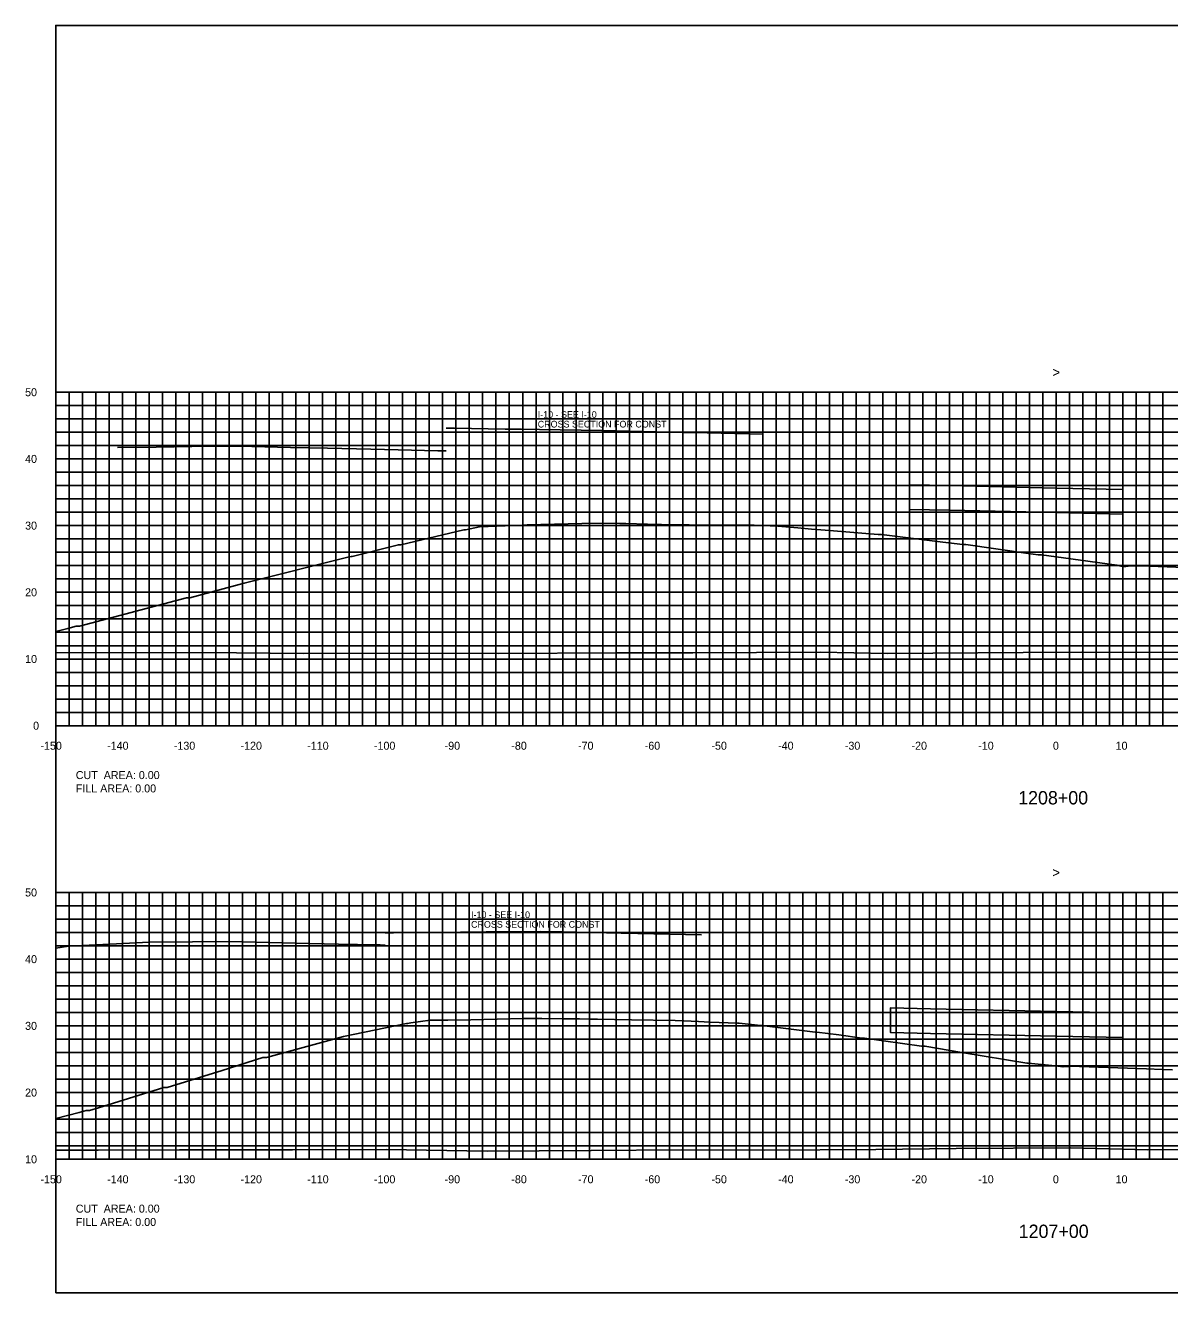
# Model space of a CAD drawing. Extents: x 1797305 to 1804485, y 245831 to 250849.
# Drawn here: x 1803156.4 to 1803328, y 250079.4 to 250269.4 of the extents above; entities that cross this region are included whole.
import ezdxf

# ---------------------------------------------------------------- set-up
doc = ezdxf.new("R2010")
doc.units = 0
for name, color, linetype in [('1', 7, 'Continuous'), ('10', 7, 'Continuous'), ('29', 7, 'Continuous'), ('60', 7, 'Continuous'), ('CL-CNST', 7, 'Continuous'), ('EDPV-LINE', 7, 'Continuous'), ('Level 31', 7, 'Continuous'), ('LIMT-CSLINE', 7, 'Continuous'), ('M-ROADS', 7, 'Continuous'), ('SURVEY - DRAINAGE - Area Shapes', 7, 'Continuous')]:
    doc.layers.add(name, color=color, linetype=linetype)

msp = doc.modelspace()

# ---------------------------------------------------------------- linework, layer by layer
msp.add_lwpolyline([(1803161, 250079.43), (1803461, 250079.43), (1803461, 250269.43), (1803161, 250269.43)], close=True)
at = {"layer": '29'}
for p, q in [((1803161, 250214.43), (1803461, 250214.43)), ((1803161, 250164.43), (1803161, 250214.43)), ((1803163, 250164.43), (1803163, 250214.43)), ((1803165, 250164.43), (1803165, 250214.43)), ((1803167, 250164.43), (1803167, 250214.43)), ((1803169, 250164.43), (1803169, 250214.43)), ((1803171, 250164.43), (1803171, 250214.43)), ((1803173, 250164.43), (1803173, 250214.43)), ((1803175, 250164.43), (1803175, 250214.43)), ((1803177, 250164.43), (1803177, 250214.43)), ((1803179, 250164.43), (1803179, 250214.43)), ((1803181, 250164.43), (1803181, 250214.43)), ((1803183, 250164.43), (1803183, 250214.43)), ((1803185, 250164.43), (1803185, 250214.43)), ((1803187, 250164.43), (1803187, 250214.43)), ((1803189, 250164.43), (1803189, 250214.43)), ((1803191, 250164.43), (1803191, 250214.43)), ((1803193, 250164.43), (1803193, 250214.43)), ((1803195, 250164.43), (1803195, 250214.43)), ((1803197, 250164.43), (1803197, 250214.43)), ((1803199, 250164.43), (1803199, 250214.43)), ((1803201, 250164.43), (1803201, 250214.43)), ((1803203, 250164.43), (1803203, 250214.43)), ((1803205, 250164.43), (1803205, 250214.43)), ((1803207, 250164.43), (1803207, 250214.43)), ((1803209, 250164.43), (1803209, 250214.43)), ((1803211, 250164.43), (1803211, 250214.43)), ((1803213, 250164.43), (1803213, 250214.43)), ((1803215, 250164.43), (1803215, 250214.43)), ((1803217, 250164.43), (1803217, 250214.43)), ((1803219, 250164.43), (1803219, 250214.43)), ((1803221, 250164.43), (1803221, 250214.43)), ((1803223, 250164.43), (1803223, 250214.43)), ((1803225, 250164.43), (1803225, 250214.43)), ((1803227, 250164.43), (1803227, 250214.43)), ((1803229, 250164.43), (1803229, 250214.43)), ((1803231, 250164.43), (1803231, 250214.43)), ((1803233, 250164.43), (1803233, 250214.43)), ((1803235, 250164.43), (1803235, 250214.43)), ((1803237, 250164.43), (1803237, 250214.43)), ((1803239, 250164.43), (1803239, 250214.43)), ((1803241, 250164.43), (1803241, 250214.43)), ((1803243, 250164.43), (1803243, 250214.43)), ((1803245, 250164.43), (1803245, 250214.43)), ((1803247, 250164.43), (1803247, 250214.43)), ((1803249, 250164.43), (1803249, 250214.43)), ((1803251, 250164.43), (1803251, 250214.43)), ((1803253, 250164.43), (1803253, 250214.43)), ((1803255, 250164.43), (1803255, 250214.43)), ((1803257, 250164.43), (1803257, 250214.43)), ((1803259, 250164.43), (1803259, 250214.43)), ((1803261, 250164.43), (1803261, 250214.43)), ((1803263, 250164.43), (1803263, 250214.43)), ((1803265, 250164.43), (1803265, 250214.43)), ((1803267, 250164.43), (1803267, 250214.43)), ((1803269, 250164.43), (1803269, 250214.43)), ((1803271, 250164.43), (1803271, 250214.43)), ((1803273, 250164.43), (1803273, 250214.43)), ((1803275, 250164.43), (1803275, 250214.43)), ((1803277, 250164.43), (1803277, 250214.43)), ((1803279, 250164.43), (1803279, 250214.43)), ((1803281, 250164.43), (1803281, 250214.43)), ((1803283, 250164.43), (1803283, 250214.43)), ((1803285, 250164.43), (1803285, 250214.43)), ((1803287, 250164.43), (1803287, 250214.43)), ((1803289, 250164.43), (1803289, 250214.43)), ((1803291, 250164.43), (1803291, 250214.43)), ((1803293, 250164.43), (1803293, 250214.43)), ((1803295, 250164.43), (1803295, 250214.43)), ((1803297, 250164.43), (1803297, 250214.43)), ((1803299, 250164.43), (1803299, 250214.43)), ((1803301, 250164.43), (1803301, 250214.43)), ((1803303, 250164.43), (1803303, 250214.43)), ((1803305, 250164.43), (1803305, 250214.43)), ((1803307, 250164.43), (1803307, 250214.43)), ((1803309, 250164.43), (1803309, 250214.43)), ((1803311, 250164.43), (1803311, 250214.43)), ((1803313, 250164.43), (1803313, 250214.43)), ((1803315, 250164.43), (1803315, 250214.43)), ((1803317, 250164.43), (1803317, 250214.43)), ((1803319, 250164.43), (1803319, 250214.43)), ((1803321, 250164.43), (1803321, 250214.43)), ((1803323, 250164.43), (1803323, 250214.43)), ((1803325, 250164.43), (1803325, 250214.43)), ((1803327, 250164.43), (1803327, 250214.43)), ((1803161, 250212.43), (1803461, 250212.43)), ((1803161, 250210.43), (1803461, 250210.43)), ((1803161, 250208.43), (1803461, 250208.43)), ((1803161, 250206.43), (1803461, 250206.43)), ((1803161, 250204.43), (1803461, 250204.43)), ((1803161, 250202.43), (1803461, 250202.43)), ((1803161, 250200.43), (1803461, 250200.43)), ((1803161, 250198.43), (1803461, 250198.43)), ((1803161, 250196.43), (1803461, 250196.43)), ((1803161, 250194.43), (1803461, 250194.43)), ((1803161, 250192.43), (1803461, 250192.43)), ((1803161, 250190.43), (1803461, 250190.43)), ((1803161, 250188.43), (1803461, 250188.43)), ((1803161, 250186.43), (1803461, 250186.43)), ((1803161, 250184.43), (1803461, 250184.43)), ((1803161, 250182.43), (1803461, 250182.43)), ((1803161, 250180.43), (1803461, 250180.43)), ((1803161, 250178.43), (1803461, 250178.43)), ((1803161, 250176.43), (1803461, 250176.43)), ((1803161, 250174.43), (1803461, 250174.43)), ((1803161, 250172.43), (1803461, 250172.43)), ((1803161, 250170.43), (1803461, 250170.43)), ((1803161, 250168.43), (1803461, 250168.43)), ((1803161, 250166.43), (1803461, 250166.43)), ((1803161, 250164.43), (1803461, 250164.43)), ((1803161, 250139.43), (1803461, 250139.43)), ((1803161, 250099.43), (1803161, 250139.43)), ((1803163, 250099.43), (1803163, 250139.43)), ((1803165, 250099.43), (1803165, 250139.43)), ((1803167, 250099.43), (1803167, 250139.43)), ((1803169, 250099.43), (1803169, 250139.43)), ((1803171, 250099.43), (1803171, 250139.43)), ((1803173, 250099.43), (1803173, 250139.43)), ((1803175, 250099.43), (1803175, 250139.43)), ((1803177, 250099.43), (1803177, 250139.43)), ((1803179, 250099.43), (1803179, 250139.43)), ((1803181, 250099.43), (1803181, 250139.43)), ((1803183, 250099.43), (1803183, 250139.43)), ((1803185, 250099.43), (1803185, 250139.43)), ((1803187, 250099.43), (1803187, 250139.43)), ((1803189, 250099.43), (1803189, 250139.43)), ((1803191, 250099.43), (1803191, 250139.43)), ((1803193, 250099.43), (1803193, 250139.43)), ((1803195, 250099.43), (1803195, 250139.43)), ((1803197, 250099.43), (1803197, 250139.43)), ((1803199, 250099.43), (1803199, 250139.43)), ((1803201, 250099.43), (1803201, 250139.43)), ((1803203, 250099.43), (1803203, 250139.43)), ((1803205, 250099.43), (1803205, 250139.43)), ((1803207, 250099.43), (1803207, 250139.43)), ((1803209, 250099.43), (1803209, 250139.43)), ((1803211, 250099.43), (1803211, 250139.43)), ((1803213, 250099.43), (1803213, 250139.43)), ((1803215, 250099.43), (1803215, 250139.43)), ((1803217, 250099.43), (1803217, 250139.43)), ((1803219, 250099.43), (1803219, 250139.43)), ((1803221, 250099.43), (1803221, 250139.43)), ((1803223, 250099.43), (1803223, 250139.43)), ((1803225, 250099.43), (1803225, 250139.43)), ((1803227, 250099.43), (1803227, 250139.43)), ((1803229, 250099.43), (1803229, 250139.43)), ((1803231, 250099.43), (1803231, 250139.43)), ((1803233, 250099.43), (1803233, 250139.43)), ((1803235, 250099.43), (1803235, 250139.43)), ((1803237, 250099.43), (1803237, 250139.43)), ((1803239, 250099.43), (1803239, 250139.43)), ((1803241, 250099.43), (1803241, 250139.43)), ((1803243, 250099.43), (1803243, 250139.43)), ((1803245, 250099.43), (1803245, 250139.43)), ((1803247, 250099.43), (1803247, 250139.43)), ((1803249, 250099.43), (1803249, 250139.43)), ((1803251, 250099.43), (1803251, 250139.43)), ((1803253, 250099.43), (1803253, 250139.43)), ((1803255, 250099.43), (1803255, 250139.43)), ((1803257, 250099.43), (1803257, 250139.43)), ((1803259, 250099.43), (1803259, 250139.43)), ((1803261, 250099.43), (1803261, 250139.43)), ((1803263, 250099.43), (1803263, 250139.43)), ((1803265, 250099.43), (1803265, 250139.43)), ((1803267, 250099.43), (1803267, 250139.43)), ((1803269, 250099.43), (1803269, 250139.43)), ((1803271, 250099.43), (1803271, 250139.43)), ((1803273, 250099.43), (1803273, 250139.43)), ((1803275, 250099.43), (1803275, 250139.43)), ((1803277, 250099.43), (1803277, 250139.43)), ((1803279, 250099.43), (1803279, 250139.43)), ((1803281, 250099.43), (1803281, 250139.43)), ((1803283, 250099.43), (1803283, 250139.43)), ((1803285, 250099.43), (1803285, 250139.43)), ((1803287, 250099.43), (1803287, 250139.43)), ((1803289, 250099.43), (1803289, 250139.43)), ((1803291, 250099.43), (1803291, 250139.43)), ((1803293, 250099.43), (1803293, 250139.43)), ((1803295, 250099.43), (1803295, 250139.43)), ((1803297, 250099.43), (1803297, 250139.43)), ((1803299, 250099.43), (1803299, 250139.43)), ((1803301, 250099.43), (1803301, 250139.43)), ((1803303, 250099.43), (1803303, 250139.43)), ((1803305, 250099.43), (1803305, 250139.43)), ((1803307, 250099.43), (1803307, 250139.43)), ((1803309, 250099.43), (1803309, 250139.43)), ((1803311, 250099.43), (1803311, 250139.43)), ((1803313, 250099.43), (1803313, 250139.43)), ((1803315, 250099.43), (1803315, 250139.43)), ((1803317, 250099.43), (1803317, 250139.43)), ((1803319, 250099.43), (1803319, 250139.43)), ((1803321, 250099.43), (1803321, 250139.43)), ((1803323, 250099.43), (1803323, 250139.43)), ((1803325, 250099.43), (1803325, 250139.43)), ((1803327, 250099.43), (1803327, 250139.43)), ((1803161, 250137.43), (1803461, 250137.43)), ((1803161, 250135.43), (1803461, 250135.43)), ((1803161, 250133.43), (1803461, 250133.43)), ((1803161, 250131.43), (1803461, 250131.43)), ((1803161, 250129.43), (1803461, 250129.43)), ((1803161, 250127.43), (1803461, 250127.43)), ((1803161, 250125.43), (1803461, 250125.43)), ((1803161, 250123.43), (1803461, 250123.43)), ((1803161, 250121.43), (1803461, 250121.43)), ((1803161, 250119.43), (1803461, 250119.43)), ((1803161, 250117.43), (1803461, 250117.43)), ((1803161, 250115.43), (1803461, 250115.43)), ((1803161, 250113.43), (1803461, 250113.43)), ((1803161, 250111.43), (1803461, 250111.43)), ((1803161, 250109.43), (1803461, 250109.43)), ((1803161, 250107.43), (1803461, 250107.43)), ((1803161, 250105.43), (1803461, 250105.43)), ((1803161, 250103.43), (1803461, 250103.43)), ((1803161, 250101.43), (1803461, 250101.43)), ((1803161, 250099.43), (1803461, 250099.43))]:
    msp.add_line(p, q, dxfattribs=at)
at = {"layer": 'CL-CNST'}
for points in [[(1803219.52, 250209.04), (1803219.86, 250209.04), (1803220.77, 250209.03), (1803228.37, 250208.9), (1803230.81, 250208.87), (1803233.52, 250208.84), (1803242.86, 250208.68), (1803245.07, 250208.63), (1803254.91, 250208.41), (1803256.61, 250208.38), (1803266.96, 250208.15)], [(1803170.24, 250206.16), (1803176.03, 250206.18), (1803184.12, 250206.35), (1803190.38, 250206.27), (1803196.17, 250206.16), (1803201.75, 250206.03), (1803208.22, 250205.89), (1803212.34, 250205.79), (1803218.26, 250205.66), (1803218.74, 250205.64), (1803219.51, 250205.63)], [(1803289, 250200.55), (1803295, 250200.42), (1803311, 250200.06), (1803321, 250199.84)], [(1803161, 250175.43), (1803169.05, 250175.38), (1803183.05, 250175.39), (1803198.21, 250175.28), (1803214.17, 250175.32), (1803227.37, 250175.28), (1803245.01, 250175.35), (1803256.53, 250175.36), (1803275.61, 250175.45), (1803285.69, 250175.28), (1803306.02, 250175.39), (1803314.85, 250175.47), (1803322.91, 250175.42), (1803344, 250175.54), (1803351.63, 250175.66), (1803373.16, 250175.77), (1803380.31, 250175.58), (1803402.32, 250175.72), (1803412.2, 250175.39), (1803431.48, 250175.52), (1803440.95, 250175.52), (1803460.64, 250175.64), (1803461, 250175.64)], [(1803210.36, 250133.39), (1803211.12, 250133.4), (1803211.62, 250133.4), (1803215.36, 250133.45), (1803221.66, 250133.49), (1803225.54, 250133.54), (1803233.71, 250133.6), (1803236.92, 250133.53), (1803245.76, 250133.34), (1803248.29, 250133.28), (1803257.81, 250133.08)], [(1803161, 250131.06), (1803162.92, 250131.38), (1803170.11, 250131.73), (1803174.97, 250131.97), (1803181.48, 250132.04), (1803187.02, 250132.07), (1803192.85, 250131.94), (1803199.07, 250131.8), (1803203.4, 250131.7), (1803209.11, 250131.58), (1803209.61, 250131.57), (1803210.36, 250131.55)], [(1803286.14, 250122.12), (1803292.14, 250121.99), (1803311, 250121.58), (1803321, 250121.36)], [(1803161, 250100.79), (1803167.34, 250100.77), (1803179.55, 250100.82), (1803196.5, 250100.83), (1803210.52, 250100.9), (1803225.66, 250100.64), (1803241.27, 250100.73), (1803254.82, 250100.86), (1803267.21, 250100.78), (1803283.97, 250100.87), (1803295.99, 250101.06), (1803313.13, 250101.15), (1803324.73, 250100.85), (1803342.29, 250100.95), (1803358.84, 250100.4), (1803371.45, 250100.49), (1803387.93, 250100.49), (1803400.61, 250100.57), (1803416.68, 250100.57), (1803429.77, 250100.62), (1803444.97, 250100.63), (1803458.93, 250100.66), (1803461, 250100.66)]]:
    msp.add_lwpolyline(points, dxfattribs=at)
at = {"layer": 'Level 31'}
for p, q in [((1803160.94, 250214.43), (1803161, 250214.43)), ((1803161, 250164.43), (1803161, 250214.43)), ((1803160.94, 250204.43), (1803161, 250204.43)), ((1803160.94, 250194.43), (1803161, 250194.43)), ((1803160.94, 250184.43), (1803161, 250184.43)), ((1803160.94, 250174.43), (1803161, 250174.43)), ((1803160.94, 250164.43), (1803161, 250164.43)), ((1803161, 250164.43), (1803461, 250164.43)), ((1803161, 250164.37), (1803161, 250164.43)), ((1803171, 250164.37), (1803171, 250164.43)), ((1803181, 250164.37), (1803181, 250164.43)), ((1803191, 250164.37), (1803191, 250164.43)), ((1803201, 250164.37), (1803201, 250164.43)), ((1803211, 250164.37), (1803211, 250164.43)), ((1803221, 250164.37), (1803221, 250164.43)), ((1803231, 250164.37), (1803231, 250164.43)), ((1803241, 250164.37), (1803241, 250164.43)), ((1803251, 250164.37), (1803251, 250164.43)), ((1803261, 250164.37), (1803261, 250164.43)), ((1803271, 250164.37), (1803271, 250164.43)), ((1803281, 250164.37), (1803281, 250164.43)), ((1803291, 250164.37), (1803291, 250164.43)), ((1803301, 250164.37), (1803301, 250164.43)), ((1803311, 250164.37), (1803311, 250164.43)), ((1803321, 250164.37), (1803321, 250164.43)), ((1803160.94, 250139.43), (1803161, 250139.43)), ((1803161, 250099.43), (1803161, 250139.43)), ((1803160.94, 250129.43), (1803161, 250129.43)), ((1803160.94, 250119.43), (1803161, 250119.43)), ((1803160.94, 250109.43), (1803161, 250109.43)), ((1803160.94, 250099.43), (1803161, 250099.43)), ((1803161, 250099.43), (1803461, 250099.43)), ((1803161, 250099.37), (1803161, 250099.43)), ((1803171, 250099.37), (1803171, 250099.43)), ((1803181, 250099.37), (1803181, 250099.43)), ((1803191, 250099.37), (1803191, 250099.43)), ((1803201, 250099.37), (1803201, 250099.43)), ((1803211, 250099.37), (1803211, 250099.43)), ((1803221, 250099.37), (1803221, 250099.43)), ((1803231, 250099.37), (1803231, 250099.43)), ((1803241, 250099.37), (1803241, 250099.43)), ((1803251, 250099.37), (1803251, 250099.43)), ((1803261, 250099.37), (1803261, 250099.43)), ((1803271, 250099.37), (1803271, 250099.43)), ((1803281, 250099.37), (1803281, 250099.43)), ((1803291, 250099.37), (1803291, 250099.43)), ((1803301, 250099.37), (1803301, 250099.43)), ((1803311, 250099.37), (1803311, 250099.43)), ((1803321, 250099.37), (1803321, 250099.43))]:
    msp.add_line(p, q, dxfattribs=at)
at = {"layer": 'M-ROADS'}
for points in [[(1803161, 250178.54), (1803162.82, 250179), (1803164.08, 250179.33), (1803164.57, 250179.33), (1803180.61, 250183.61), (1803180.77, 250183.61), (1803181.1, 250183.61), (1803189.25, 250185.78), (1803205.01, 250189.76), (1803205.3, 250189.82), (1803205.46, 250189.82), (1803212.37, 250191.57), (1803212.71, 250191.57), (1803222.19, 250193.8), (1803222.43, 250193.8), (1803224.52, 250194.23), (1803230.98, 250194.5), (1803231.65, 250194.55), (1803239.89, 250194.74), (1803243.07, 250194.82), (1803245.59, 250194.76), (1803246.45, 250194.74), (1803249.71, 250194.65), (1803253.93, 250194.55), (1803255.98, 250194.55), (1803259.86, 250194.52), (1803263.69, 250194.5), (1803265.73, 250194.49), (1803266.95, 250194.43), (1803269.26, 250194.35), (1803272.27, 250194.09), (1803274.29, 250193.91), (1803275.7, 250193.8), (1803277.59, 250193.64), (1803284.31, 250193.08), (1803284.65, 250193.08), (1803284.8, 250193.08), (1803293.98, 250191.95), (1803296.97, 250191.58), (1803297.34, 250191.58), (1803297.46, 250191.58), (1803306.8, 250190.26), (1803308.3, 250190.05), (1803308.74, 250190.05), (1803308.79, 250190.05), (1803312.1, 250189.61), (1803314.62, 250189.26), (1803320.08, 250188.5), (1803320.12, 250188.49), (1803320.2, 250188.46), (1803320.28, 250188.43), (1803321.1, 250188.26), (1803322.12, 250188.42), (1803323.61, 250188.39), (1803332.94, 250188.03)], [(1803161, 250105.55), (1803164.52, 250106.44), (1803165.55, 250106.73), (1803165.99, 250106.73), (1803166.05, 250106.73), (1803167.41, 250107.13), (1803177.21, 250110.17), (1803177.58, 250110.18), (1803177.71, 250110.18), (1803185.95, 250112.73), (1803192.06, 250114.68), (1803192.4, 250114.68), (1803192.58, 250114.69), (1803204.12, 250117.86), (1803213.59, 250119.77), (1803213.74, 250119.77), (1803214.24, 250119.88), (1803217.14, 250120.27), (1803217.69, 250120.27), (1803217.97, 250120.27), (1803219.77, 250120.26), (1803223.21, 250120.35), (1803231.14, 250120.54), (1803232.07, 250120.53), (1803233.85, 250120.52), (1803237.13, 250120.49), (1803239.54, 250120.47), (1803240.94, 250120.45), (1803242.23, 250120.44), (1803247.3, 250120.34), (1803253.84, 250120.24), (1803255.18, 250120.19), (1803257.36, 250120.1), (1803259.04, 250119.99), (1803263.21, 250119.85), (1803263.46, 250119.85), (1803266.67, 250119.47), (1803266.88, 250119.47), (1803274.83, 250118.5), (1803275.1, 250118.47), (1803278.42, 250118.07), (1803281.84, 250117.61), (1803282.27, 250117.61), (1803290.81, 250116.41), (1803291.13, 250116.41), (1803291.31, 250116.41), (1803296.86, 250115.46), (1803306.59, 250113.84), (1803306.81, 250113.84), (1803310.84, 250113.46), (1803310.9, 250113.45), (1803312, 250113.3), (1803312.02, 250113.3), (1803312.35, 250113.35), (1803312.87, 250113.36), (1803312.89, 250113.37), (1803312.92, 250113.37), (1803312.96, 250113.37), (1803313, 250113.37), (1803313.06, 250113.38), (1803313.14, 250113.38), (1803313.25, 250113.39), (1803313.28, 250113.39), (1803314.47, 250113.35), (1803324.52, 250112.99), (1803326.87, 250112.91), (1803326.97, 250112.9), (1803328.41, 250112.83)]]:
    msp.add_lwpolyline(points, dxfattribs=at)
at = {"layer": 'SURVEY - DRAINAGE - Area Shapes'}
for points in [[(1803321, 250196.16), (1803321, 250199.84), (1803311, 250200.06), (1803295, 250200.42), (1803289, 250200.55), (1803289, 250196.87), (1803295, 250196.74), (1803311, 250196.38)], [(1803321, 250117.68), (1803321, 250121.36), (1803311, 250121.58), (1803292.14, 250121.99), (1803286.14, 250122.12), (1803286.14, 250118.44), (1803292.14, 250118.31), (1803311, 250117.9)]]:
    msp.add_lwpolyline(points, close=True, dxfattribs=at)

# ---------------------------------------------------------------- texts
at = {"layer": '1'}
for s, p in [('1208+00', (1803305.29, 250152.63)), ('1207+00', (1803305.37, 250087.63))]:
    msp.add_text(s, height=2, dxfattribs=at).set_placement(p)
at = {"layer": '10'}
for s, p in [('-150', (1803158.7, 250160.83)), ('-140', (1803168.7, 250160.83)), ('-130', (1803178.7, 250160.83)), ('-120', (1803188.7, 250160.83)), ('-110', (1803198.7, 250160.83)), ('-100', (1803208.7, 250160.83)), ('-90', (1803219.3, 250160.83)), ('-80', (1803229.3, 250160.83)), ('-70', (1803239.3, 250160.83)), ('-60', (1803249.3, 250160.83)), ('-50', (1803259.3, 250160.83)), ('-40', (1803269.3, 250160.83)), ('-30', (1803279.3, 250160.83)), ('-20', (1803289.3, 250160.83)), ('-10', (1803299.3, 250160.83)), ('0', (1803310.5, 250160.83)), ('10', (1803319.9, 250160.83)), ('-150', (1803158.7, 250095.83)), ('-140', (1803168.7, 250095.83)), ('-130', (1803178.7, 250095.83)), ('-120', (1803188.7, 250095.83)), ('-110', (1803198.7, 250095.83)), ('-100', (1803208.7, 250095.83)), ('-90', (1803219.3, 250095.83)), ('-80', (1803229.3, 250095.83)), ('-70', (1803239.3, 250095.83)), ('-60', (1803249.3, 250095.83)), ('-50', (1803259.3, 250095.83)), ('-40', (1803269.3, 250095.83)), ('-30', (1803279.3, 250095.83)), ('-20', (1803289.3, 250095.83)), ('-10', (1803299.3, 250095.83)), ('0', (1803310.5, 250095.83)), ('10', (1803319.9, 250095.83))]:
    msp.add_text(s, height=1.2, dxfattribs=at).set_placement(p)
at = {"layer": '60'}
for s, p in [('50', (1803156.4, 250213.83)), ('40', (1803156.4, 250203.83)), ('30', (1803156.4, 250193.83)), ('20', (1803156.4, 250183.83)), ('10', (1803156.4, 250173.83)), ('0', (1803157.6, 250163.83)), ('50', (1803156.4, 250138.83)), ('40', (1803156.4, 250128.83)), ('30', (1803156.4, 250118.83)), ('20', (1803156.4, 250108.83)), ('10', (1803156.4, 250098.83))]:
    msp.add_text(s, height=1.2, dxfattribs=at).set_placement(p)
at = {"layer": 'EDPV-LINE'}
for s, p in [('CUT  AREA: 0.00', (1803164, 250156.43)), ('FILL AREA: 0.00', (1803164, 250154.43)), ('CUT  AREA: 0.00', (1803164, 250091.43)), ('FILL AREA: 0.00', (1803164, 250089.43))]:
    msp.add_text(s, height=1.2, dxfattribs=at).set_placement(p)
at = {"layer": 'Level 31'}
for s, height, p in [('>', 1.5, (1803310.39, 250216.68)), ('-', 0.0001, (1803161, 250164.43)), ('>', 1.5, (1803310.39, 250141.68)), ('-', 0.0001, (1803161, 250099.43))]:
    msp.add_text(s, height=height, dxfattribs=at).set_placement(p)
at = {"layer": 'LIMT-CSLINE'}
for s, p in [('I-10 - SEE I-10', (1803233.26, 250210.59)), ('CROSS SECTION FOR CONST ', (1803233.26, 250209.14)), ('CROSS SECTION FOR CONST ', (1803223.26, 250134.14)), ('I-10 - SEE I-10', (1803223.26, 250135.59))]:
    msp.add_text(s, height=1, dxfattribs=at).set_placement(p)

doc.saveas('drawing.dxf')
